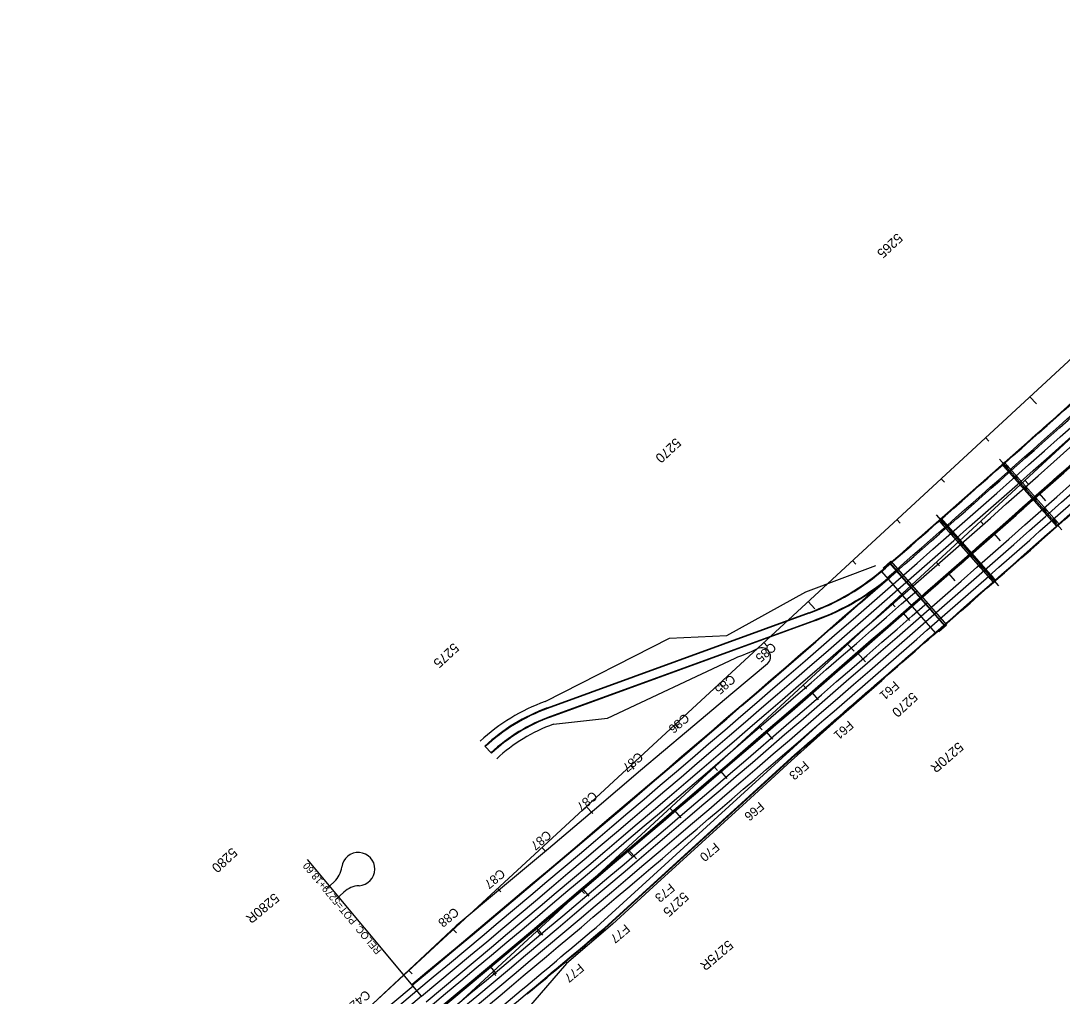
# Model space of a CAD drawing. Extents: x 2160877 to 2175861, y 601747 to 617724.
# Drawn here: x 2163672 to 2165397, y 606444 to 608059 of the extents above; entities that cross this region are included whole.
import ezdxf

# ---------------------------------------------------------------- set-up
doc = ezdxf.new("R2010")
doc.units = 0
for name, color, linetype in [('BR_CENTER LINES', 7, 'Continuous'), ('BR_CONCRETE', 7, 'Continuous'), ('RD_HC_Cl', 7, 'Continuous'), ('RD_HC_CL_Rel', 7, 'Continuous'), ('RD_HC_Data_Rel', 7, 'Continuous'), ('RD_HC_Data_Tic', 7, 'Continuous'), ('RD_HC_Data_Tic_Rel', 7, 'Continuous'), ('RD_HC_TX_Rel_Sta50', 7, 'Continuous'), ('RD_HC_TX_StaOther', 7, 'Continuous'), ('RD_PD_CstnLmt', 7, 'Continuous'), ('RD_PD_CstnLmt_TX', 7, 'Continuous'), ('RD_PD_Final_LnLine', 7, 'Continuous'), ('RD_PD_Final_TrvlWay', 7, 'Continuous'), ('RD_PD_MedBWall', 7, 'Continuous')]:
    doc.layers.add(name, color=color, linetype=linetype)

msp = doc.modelspace()

# ---------------------------------------------------------------- linework, layer by layer
at = {"layer": 'BR_CENTER LINES'}
for p, q in [((2165292.6, 607333.7), (2165396.1, 607216.7)), ((2165187.8, 607241.2), (2165291, 607124))]:
    msp.add_line(p, q, dxfattribs=at)
at = {"layer": 'BR_CONCRETE'}
for p, q in [((2165113, 607164.4), (2165100.2, 607153.2)), ((2165111.8, 607161.4), (2165101.2, 607152.1)), ((2165110.4, 607162.1), (2165202.5, 607056.8)), ((2165111.8, 607161.4), (2165202, 607058.3)), ((2165113, 607164.4), (2165205.1, 607059.1)), ((2165096.9, 607148.2), (2165186.9, 607045.2)), ((2165100.2, 607153.2), (2165101.2, 607152.1)), ((2165191.3, 607049), (2165202, 607058.3)), ((2165192.3, 607047.9), (2165205.1, 607059.1)), ((2165192.3, 607047.9), (2165191.3, 607049))]:
    msp.add_line(p, q, dxfattribs=at)
for points in [[(2165301.3, 607328), (2165297.2, 607324.4), (2165387.4, 607222.4), (2165391.6, 607226)], [(2165196.5, 607235.6), (2165192.4, 607231.9), (2165282.3, 607129.7), (2165286.4, 607133.3)]]:
    msp.add_lwpolyline(points, close=True, dxfattribs=at)
for centre, radius in [((2165304.1, 607320.7), 3), ((2165304.1, 607320.7), 2), ((2165319.7, 607303.1), 3), ((2165319.7, 607303.1), 2), ((2165335.3, 607285.5), 3), ((2165335.3, 607285.5), 2), ((2165350.8, 607267.9), 3), ((2165350.8, 607267.9), 2), ((2165367.4, 607249.2), 3), ((2165367.4, 607249.2), 2), ((2165199.3, 607228.2), 3), ((2165199.3, 607228.2), 2), ((2165384, 607230.5), 3), ((2165384, 607230.5), 2), ((2165214.8, 607210.6), 3), ((2165214.8, 607210.6), 2), ((2165230.3, 607192.9), 3), ((2165230.3, 607192.9), 2), ((2165245.8, 607175.3), 3), ((2165245.8, 607175.3), 2), ((2165262.3, 607156.5), 3), ((2165262.3, 607156.5), 2), ((2165278.9, 607137.7), 3), ((2165278.9, 607137.7), 2)]:
    msp.add_circle(centre, radius, dxfattribs=at)
for radius, start in [(44223.5, 311.14908), (44238.5, 311.14908), (44240.8, 311.14908), (44298.8, 311.14908), (44301.2, 311.14908), (44359.2, 311.14907), (44360.2, 311.14907), (44360.3, 311.14907)]:
    msp.add_arc((2135996.9, 640448.5), radius, start, 312.71947, dxfattribs=at)
at = {"layer": 'RD_HC_Cl'}
for p, q in [((2172207.3, 613775.1), (2163672.2, 605893.8)), ((2172272.5, 613704.6), (2163737.4, 605823.3))]:
    msp.add_line(p, q, dxfattribs=at)
at = {"layer": 'RD_HC_CL_Rel'}
msp.add_line((2164335.8, 606444.4), (2163946.7, 606120.1), dxfattribs=at)
msp.add_arc((2135996.9, 640448.5), 44300, 309.80773, 312.71947, dxfattribs=at)
at = {"layer": 'RD_HC_Data_Rel'}
msp.add_line((2164335.8, 606444.4), (2164147.1, 606670.9), dxfattribs=at)
at = {"layer": 'RD_HC_Data_Tic'}
for p, q in [((2165343.3, 607436.9), (2165354.2, 607425.1)), ((2165269.8, 607369.1), (2165275.3, 607363.2)), ((2165196.4, 607301.2), (2165201.8, 607295.3)), ((2165335, 607298.5), (2165340.4, 607292.7)), ((2165122.9, 607233.4), (2165128.3, 607227.5)), ((2165261.5, 607230.7), (2165266.9, 607224.8)), ((2165049.4, 607165.5), (2165054.9, 607159.7)), ((2165188, 607162.8), (2165193.5, 607157)), ((2164976, 607097.7), (2164986.8, 607085.9)), ((2165114.6, 607095), (2165120, 607089.1)), ((2164902.5, 607029.9), (2164907.9, 607024)), ((2165041.1, 607027.2), (2165052, 607015.4)), ((2164829, 606962), (2164834.5, 606956.1)), ((2164967.6, 606959.3), (2164973.1, 606953.4)), ((2164755.6, 606894.2), (2164761, 606888.3)), ((2164894.2, 606891.5), (2164899.6, 606885.6)), ((2164682.1, 606826.3), (2164687.5, 606820.5)), ((2164820.7, 606823.6), (2164826.1, 606817.8)), ((2164608.6, 606758.5), (2164619.5, 606746.7)), ((2164747.2, 606755.8), (2164752.7, 606749.9)), ((2164535.2, 606690.6), (2164540.6, 606684.8)), ((2164673.8, 606688), (2164684.6, 606676.2)), ((2164461.7, 606622.8), (2164467.1, 606616.9)), ((2164600.3, 606620.1), (2164605.7, 606614.2)), ((2164388.2, 606555), (2164393.7, 606549.1)), ((2164526.8, 606552.3), (2164532.3, 606546.4)), ((2164314.8, 606487.1), (2164320.2, 606481.2)), ((2164453.4, 606484.4), (2164458.8, 606478.6))]:
    msp.add_line(p, q, dxfattribs=at)
at = {"layer": 'RD_HC_Data_Tic_Rel'}
for p, q in [((2165358.6, 607276.5), (2165369.2, 607264.5)), ((2165283.6, 607210.3), (2165294.2, 607198.3)), ((2165208.5, 607144.3), (2165219.1, 607132.3)), ((2165133.3, 607078.4), (2165143.8, 607066.4)), ((2165057.9, 607012.8), (2165071, 606997.7)), ((2164982.3, 606947.2), (2164992.8, 606935.1)), ((2164906.6, 606881.9), (2164917.1, 606869.8)), ((2164830.8, 606816.7), (2164841.2, 606804.6)), ((2164754.8, 606751.7), (2164765.2, 606739.5)), ((2164678.6, 606686.9), (2164691.6, 606671.6)), ((2164602.4, 606622.2), (2164612.7, 606610)), ((2164525.9, 606557.7), (2164536.2, 606545.5)), ((2164449.3, 606493.4), (2164459.6, 606481.2))]:
    msp.add_line(p, q, dxfattribs=at)
at = {"layer": 'RD_PD_CstnLmt'}
for p, q in [((2164746.6, 607037.4), (2164841.3, 607041.8)), ((2164540.4, 606932.2), (2164746.6, 607037.4)), ((2164643.9, 606904.6), (2164855, 607004.2)), ((2164908.5, 606994.9), (2164851.1, 606946.4)), ((2165098, 606966.6), (2165022.3, 606901)), ((2164851.1, 606946.4), (2164774.7, 606882.1)), ((2164554.1, 606894.7), (2164643.9, 606904.6)), ((2165022.3, 606901), (2164948, 606833.8)), ((2164774.7, 606882.1), (2164698.2, 606818)), ((2164948, 606833.8), (2164874, 606766.3)), ((2164698.2, 606818), (2164622.4, 606753.1)), ((2164874, 606766.3), (2164800, 606698.8)), ((2164622.4, 606753.1), (2164546.3, 606688.5)), ((2164800, 606698.8), (2164725.9, 606631.3)), ((2164546.3, 606688.5), (2164469.6, 606624.7)), ((2164725.9, 606631.3), (2164651.8, 606563.7)), ((2164469.6, 606624.7), (2164392.9, 606560.8)), ((2164392.9, 606560.8), (2164246.7, 606424.2)), ((2164651.8, 606563.7), (2164575.6, 606498.7)), ((2164575.6, 606498.7), (2164509.5, 606421.7))]:
    msp.add_line(p, q, dxfattribs=at)
msp.add_lwpolyline([(2164841.3, 607041.8), (2164972.4, 607113.8), (2165088.2, 607157.3)], dxfattribs=at)
for centre, radius, start, end in [((2164708.5, 607406.4), 428, 290.0109, 295.4412), ((2164898.8, 607006.3), 15, 310.1627, 115.4412), ((2164649.6, 606632.5), 319, 110.0109, 132.7405), ((2164649.6, 606632.5), 279, 110.0109, 132.7405)]:
    msp.add_arc(centre, radius, start, end, dxfattribs=at)
at = {"layer": 'RD_PD_Final_LnLine'}
for p, q in [((2165001.8, 606901.7), (2164631.9, 606564.5)), ((2163939.1, 606129.3), (2164328.1, 606453.6))]:
    msp.add_line(p, q, dxfattribs=at)
for radius, start, end in [(44252.8, 309.80773, 312.71947), (44264.8, 309.80773, 312.71947), (44276.8, 309.80773, 312.71947), (44298.8, 309.80773, 312.71947), (44301.2, 309.80773, 312.71947), (44323.2, 309.80773, 312.71947), (44335.2, 309.80773, 312.71947), (44347.2, 310.84704, 312.71947), (44239.7, 309.80773, 311.15408), (44240.8, 309.80773, 311.15408), (44347.2, 309.80773, 310.84704), (44363.2, 309.80773, 310.20085)]:
    msp.add_arc((2135996.9, 640448.5), radius, start, end, dxfattribs=at)
at = {"layer": 'RD_PD_Final_TrvlWay'}
for p, q in [((2164954.1, 606844.7), (2164638.5, 606557)), ((2164954.8, 606843.8), (2164639.3, 606556.2)), ((2164178, 606621.8), (2164191.1, 606633.9)), ((2164178, 606621.8), (2164191.1, 606633.9)), ((2164194.4, 606604.9), (2164207.2, 606616.7)), ((2164194.4, 606604.9), (2164207.2, 606616.7)), ((2163932.7, 606137), (2164321.7, 606461.3)), ((2164321.7, 606461.3), (2164320.5, 606462.8)), ((2164321.7, 606461.3), (2164320.5, 606462.8))]:
    msp.add_line(p, q, dxfattribs=at)
for centre, radius, start, end in [((2135996.9, 640448.5), 44286.8, 309.80773, 311.17861), ((2135996.9, 640448.5), 44313.2, 309.80773, 311.17861), ((2136000.8, 640444), 44353.2, 310.7522, 311.15415), ((2136000.8, 640444), 44354.3, 310.75222, 311.15415), ((2164231, 606654.8), 27.5, 272.8804, 172.6984), ((2164231, 606654.8), 27.5, 272.8804, 172.6984), ((2164164, 606663.3), 40, 312.7195, 352.6984), ((2164164, 606663.3), 40, 312.7195, 352.6984), ((2164234.4, 606587.3), 40, 92.8804, 132.7195), ((2164234.4, 606587.3), 40, 92.8804, 132.7195), ((2135996.9, 640448.5), 44373.2, 309.80773, 310.2011), ((2135996.9, 640448.5), 44374.3, 309.98432, 310.20112)]:
    msp.add_arc(centre, radius, start, end, dxfattribs=at)
at = {"layer": 'RD_PD_MedBWall'}
for p, q in [((2164977.2, 607079.3), (2164544, 606921.5)), ((2164977.5, 607078.4), (2164544.3, 606920.6)), ((2164987.9, 607067.2), (2164549.1, 606907.4)), ((2164988.3, 607066.3), (2164549.5, 606906.5)), ((2164441.4, 606857.8), (2164440.7, 606858.5)), ((2164441.4, 606857.8), (2164450.9, 606847.5)), ((2164451.6, 606846.8), (2164450.9, 606847.5))]:
    msp.add_line(p, q, dxfattribs=at)
for centre, radius, start, end in [((2135996.7, 640448.7), 44223.7, 311.16011, 312.71947), ((2135996.7, 640448.7), 44224.7, 311.16011, 312.71947), ((2164840.7, 607454.2), 399, 290.0109, 311.1601), ((2164840.7, 607454.2), 400, 290.0109, 311.1601), ((2164851, 607443.1), 400, 290.0109, 311.1607), ((2164851, 607443.1), 401, 290.0109, 307.0951), ((2164649.1, 606633.1), 307, 110.0109, 132.7405), ((2164649.1, 606633.1), 306, 110.0109, 132.7405), ((2164649.1, 606633.1), 292, 110.0109, 132.7405), ((2164649.1, 606633.1), 291, 110.0109, 132.7405)]:
    msp.add_arc(centre, radius, start, end, dxfattribs=at)

# ---------------------------------------------------------------- texts
at = {"layer": 'RD_HC_Data_Rel'}
msp.add_text('RELOC. POT=5279+18.60', height=12, rotation=129.8077, dxfattribs=at).set_placement((2164270.3, 606519.9))
at = {"layer": 'RD_HC_TX_Rel_Sta50'}
for s, rotation, p in [('5270R', 220.9958, (2165224.6, 606866.2)), ('5280R', 219.8077, (2164091.9, 606616)), ('5275R', 220.3491, (2164843.5, 606538.3))]:
    msp.add_text(s, height=16, rotation=rotation, dxfattribs=at).set_placement(p)
at = {"layer": 'RD_HC_TX_StaOther'}
for s, p in [('5265', (2165123.5, 607708.7)), ('5270', (2164756.5, 607369.8)), ('5275', (2164388.8, 607030.3)), ('5270', (2165148.3, 606948.8)), ('5280', (2164021.8, 606691.4)), ('5275', (2164769.2, 606618.2))]:
    msp.add_text(s, height=16, rotation=222.7195, dxfattribs=at).set_placement(p)
at = {"layer": 'RD_PD_CstnLmt_TX'}
for s, rotation, p in [('C85', 220.7371, (2164915.2, 607031.1)), ('C85', 220.7371, (2164847.8, 606978)), ('F61', 220.9958, (2165118.8, 606967.3)), ('C86', 220.6078, (2164771.3, 606913.6)), ('F61', 220.8665, (2165043.1, 606901.6)), ('C87', 220.4785, (2164694.9, 606849.5)), ('F63', 220.7371, (2164969.4, 606834.9)), ('C87', 220.3491, (2164619.1, 606784.6)), ('F66', 220.6078, (2164895.2, 606767.2)), ('C87', 220.2198, (2164543, 606720)), ('F70', 220.4785, (2164821.3, 606699.8)), ('C87', 220.0905, (2164466.4, 606656.1)), ('F73', 220.3491, (2164747.2, 606632.2)), ('C88', 219.9611, (2164389.9, 606592.3)), ('F77', 220.2198, (2164673.1, 606564.5)), ('F77', 220.0905, (2164596.9, 606499.5)), ('C42', 219.8077, (2164243.5, 606455.5))]:
    msp.add_text(s, height=15, rotation=rotation, dxfattribs=at).set_placement(p)

doc.saveas('drawing.dxf')
